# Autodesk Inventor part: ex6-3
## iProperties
Shininess: 64.0
Length Units: 11272
Angle Units: 11279
Time Units: 11290
Mass Units: 11286
Length Display Precision: 3
Angle Display Precision: 2
Compacted: True
Part Number: ex6-3
Document SubType Name: Modeling
Created: 2002-11
Designer: Elise Moss
Density: 0.0
Volumn: 0.0
Area: 0.0
PropertySet Name: Model Information
Control State: 0
Master: False
Checked Out: False
Author: Elise Moss
